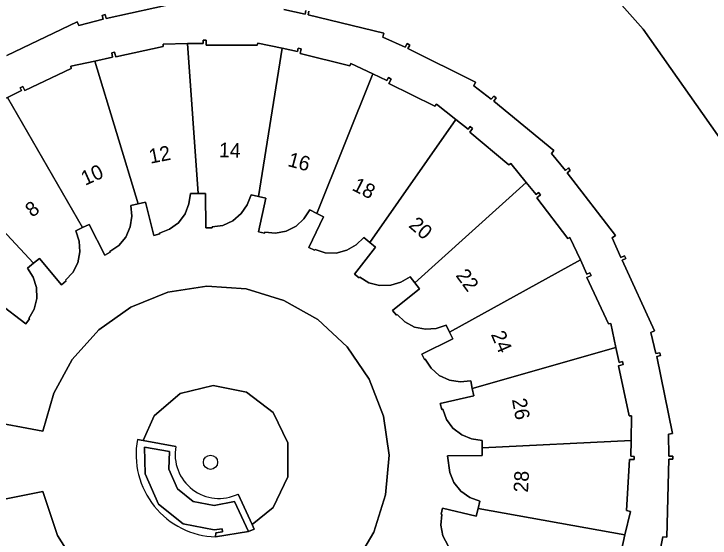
# Model space of a CAD drawing. Extents: x 156661 to 157576, y 383570 to 384425.
# Drawn here: x 157036.77 to 157084.57, y 384094.72 to 384130.69 of the extents above; entities that cross this region are included whole.
import ezdxf

# ---------------------------------------------------------------- set-up
doc = ezdxf.new("R2010")
doc.units = 0
for name, color, linetype in [('IMGEO_Boom', 7, 'Continuous'), ('IMGEO_Erf', 7, 'Continuous'), ('IMGEO_Groenvoorziening', 7, 'Continuous'), ('IMGEO_Muur', 7, 'Continuous'), ('IMGEO_Pand', 7, 'Continuous'), ('IMGEO_Pand_nummerreeks', 7, 'Continuous'), ('IMGEO_Voetpad_op_trap', 7, 'Continuous'), ('IMGEO_Voetpad_open', 7, 'Continuous')]:
    doc.layers.add(name, color=color, linetype=linetype)

msp = doc.modelspace()

# ---------------------------------------------------------------- linework, layer by layer
at = {"layer": 'IMGEO_Boom'}
msp.add_circle((157050.269, 384099.919), 0.489, dxfattribs=at)
at = {"layer": 'IMGEO_Erf'}
for points in [[(157048.127, 384131.481), (157043.095, 384130.384), (157043.028, 384130.645), (157042.825, 384130.593), (157042.892, 384130.331), (157041.237, 384129.908), (157041.118, 384130.156), (157036.279, 384127.836)], [(157056.821, 384130.939), (157056.767, 384130.675), (157055.294, 384130.999)], [(157081.016, 384093.338), (157081.32, 384094.794), (157081.594, 384094.785), (157081.74, 384100.134), (157082.004, 384100.136), (157082.002, 384100.346), (157081.732, 384100.344), (157081.712, 384101.851), (157081.981, 384101.906), (157080.903, 384107.175), (157081.167, 384107.238), (157081.114, 384107.441), (157080.852, 384107.378), (157080.506, 384108.824), (157080.756, 384108.939), (157078.531, 384113.785), (157078.779, 384113.906), (157078.69, 384114.097), (157078.447, 384113.978), (157077.845, 384115.335), (157078.07, 384115.495), (157074.758, 384119.784), (157074.967, 384119.956), (157074.843, 384120.125), (157074.634, 384119.954), (157073.675, 384121.103), (157073.85, 384121.316), (157069.713, 384124.714), (157069.878, 384124.928), (157069.712, 384125.057), (157069.547, 384124.843), (157068.349, 384125.76), (157068.471, 384126.007), (157063.82, 384128.317), (157063.951, 384128.554), (157063.767, 384128.655), (157063.636, 384128.418), (157062.103, 384129.096), (157062.167, 384129.363), (157056.97, 384130.62), (157057.026, 384130.889)], [(157036.336, 384124.956), (157037.285, 384125.441), (157037.192, 384125.629), (157037.375, 384125.722), (157037.52, 384125.433), (157040.705, 384126.94), (157040.67, 384127.096), (157042.322, 384127.458), (157043.551, 384127.728), (157043.486, 384128.025), (157043.689, 384128.077), (157043.759, 384127.755), (157047.016, 384128.46), (157047.013, 384128.62), (157048.696, 384128.653), (157049.758, 384128.674), (157049.758, 384128.894), (157049.963, 384128.895), (157049.968, 384128.557), (157053.482, 384128.539), (157053.513, 384128.69), (157055.178, 384128.34), (157056.236, 384128.118), (157056.281, 384128.332), (157056.487, 384128.289), (157056.42, 384127.967), (157059.829, 384127.14), (157059.896, 384127.285), (157061.423, 384126.576), (157062.384, 384126.129), (157062.482, 384126.321), (157062.666, 384126.22), (157062.52, 384125.924), (157065.677, 384124.365), (157065.776, 384124.491), (157067.112, 384123.451), (157067.96, 384122.79), (157068.1, 384122.96), (157068.267, 384122.832), (157068.065, 384122.57), (157070.755, 384120.324), (157070.879, 384120.426), (157071.944, 384119.12), (157072.619, 384118.293), (157072.79, 384118.432), (157072.924, 384118.27), (157072.669, 384118.06), (157074.801, 384115.28), (157074.946, 384115.347), (157075.659, 384113.804), (157076.105, 384112.84), (157076.305, 384112.932), (157076.397, 384112.743), (157076.103, 384112.593), (157077.589, 384109.42), (157077.743, 384109.453), (157078.106, 384107.804), (157078.332, 384106.778), (157078.547, 384106.826), (157078.596, 384106.621), (157078.276, 384106.541), (157079.005, 384103.114), (157079.167, 384103.112), (157079.148, 384101.408), (157079.135, 384100.331), (157079.355, 384100.328), (157079.357, 384100.118), (157079.027, 384100.116), (157078.828, 384096.611), (157079.099, 384096.548), (157078.725, 384094.94), (157078.48, 384093.889)], [(157066.574, 384094.189), (157066.219, 384094.872), (157066.086, 384095.611), (157066.157, 384096.342), (157066.099, 384096.354), (157066.187, 384096.769), (157068.518, 384096.231), (157068.635, 384096.738), (157068.752, 384097.245), (157068.073, 384097.504), (157067.465, 384097.934), (157066.973, 384098.522), (157066.689, 384099.217), (157066.549, 384100.373), (157068.91, 384100.382), (157068.916, 384100.901), (157068.923, 384101.42), (157068.195, 384101.526), (157067.519, 384101.798), (157066.902, 384102.259), (157066.462, 384102.866), (157066.208, 384103.555), (157066.15, 384103.541), (157066.047, 384103.963), (157068.347, 384104.487), (157068.24, 384104.995), (157068.133, 384105.503), (157067.4, 384105.448), (157066.68, 384105.565), (157065.978, 384105.88), (157065.415, 384106.376), (157065.017, 384106.993), (157064.963, 384106.966), (157064.775, 384107.347), (157066.895, 384108.385), (157066.674, 384108.854), (157066.453, 384109.324), (157065.752, 384109.102), (157065.025, 384109.051), (157064.27, 384109.197), (157063.608, 384109.551), (157063.079, 384110.06), (157063.033, 384110.022), (157062.765, 384110.346), (157064.609, 384111.819), (157064.292, 384112.23), (157063.974, 384112.641), (157063.338, 384112.272), (157062.64, 384112.065), (157061.87, 384112.043), (157061.148, 384112.245), (157060.521, 384112.627), (157060.484, 384112.58), (157060.159, 384112.833), (157061.607, 384114.69), (157061.203, 384115.015), (157060.799, 384115.341), (157060.266, 384114.835), (157059.634, 384114.471), (157058.891, 384114.271), (157058.141, 384114.3), (157057.443, 384114.527), (157057.418, 384114.472), (157057.019, 384114.654), (157058.024, 384116.777), (157057.558, 384117.006), (157057.093, 384117.236), (157056.683, 384116.626), (157056.147, 384116.132), (157055.465, 384115.775), (157054.727, 384115.639), (157053.996, 384115.707), (157053.984, 384115.648), (157053.563, 384115.736), (157054.061, 384118.037), (157053.556, 384118.156), (157053.05, 384118.274), (157052.79, 384117.586), (157052.379, 384116.984), (157051.796, 384116.481), (157051.108, 384116.182), (157050.381, 384116.082), (157050.382, 384116.022), (157049.952, 384116.013), (157049.93, 384118.372), (157049.411, 384118.376), (157048.892, 384118.379), (157048.789, 384117.652), (157048.522, 384116.974), (157048.065, 384116.354), (157047.46, 384115.91), (157046.772, 384115.653), (157046.787, 384115.594), (157046.381, 384115.493), (157045.812, 384117.778), (157045.3, 384117.659), (157044.788, 384117.54), (157044.858, 384116.808), (157044.755, 384116.087), (157044.455, 384115.378), (157043.97, 384114.805), (157043.361, 384114.395), (157043.389, 384114.342), (157043.012, 384114.146), (157041.945, 384116.251), (157041.479, 384116.024), (157041.012, 384115.797), (157041.243, 384115.099), (157041.304, 384114.373), (157041.169, 384113.615), (157040.824, 384112.949), (157040.322, 384112.413), (157040.361, 384112.367), (157040.038, 384112.093), (157038.527, 384113.904), (157038.119, 384113.575), (157037.712, 384113.246), (157038.094, 384112.618), (157038.316, 384111.924), (157038.354, 384111.155), (157038.167, 384110.428), (157037.799, 384109.793), (157037.847, 384109.757), (157037.593, 384109.417), (157035.706, 384110.832)], [(157034.816, 384102.793), (157038.761, 384102.061), (157039.52, 384104.666), (157040.782, 384106.976), (157042.603, 384109.015), (157044.809, 384110.57), (157047.332, 384111.598), (157050.022, 384112.012), (157052.72, 384111.821), (157055.311, 384111.02), (157057.647, 384109.712), (157059.648, 384107.839), (157061.16, 384105.616), (157062.145, 384103.084), (157062.541, 384100.402), (157062.288, 384097.687), (157061.477, 384095.127), (157060.112, 384092.793)], [(157041.241, 384092.533), (157039.761, 384094.89), (157038.769, 384097.919), (157034.843, 384097.129)]]:
    msp.add_lwpolyline(points, dxfattribs=at)
at = {"layer": 'IMGEO_Groenvoorziening'}
for points in [[(157027.895, 384067.5), (157043.532, 384046.733), (157047.525, 384049.683), (157080.513, 384071.09), (157084.345, 384074.369), (157089.926, 384085.599), (157092.747, 384099.97), (157093.567, 384107.816), (157092.136, 384111.936), (157085.938, 384121.166), (157079.977, 384129.642), (157075.189, 384135.046)], [(157075.189, 384135.046), (157079.977, 384129.642), (157085.938, 384121.166), (157092.136, 384111.936), (157093.567, 384107.816), (157092.747, 384099.97), (157089.926, 384085.599), (157084.345, 384074.369), (157087.624, 384070.536), (157154.965, 383981.147), (157118.076, 383955.713), (157048.492, 384046.401), (157047.525, 384049.683), (157043.532, 384046.733), (157050.307, 384037.736), (157052.866, 384034.354), (157120.283, 383944.64), (157124.325, 383946.137), (157128.805, 383949.146), (157133.769, 383943.405), (157129.807, 383939.447), (157125.958, 383936.438), (157125.242, 383934.934), (157125.69, 383934.221)], [(157036.279, 384127.836), (157041.118, 384130.156), (157041.237, 384129.908), (157042.892, 384130.331), (157042.825, 384130.593), (157043.028, 384130.645), (157043.095, 384130.384), (157048.127, 384131.481)], [(157055.294, 384130.999), (157056.767, 384130.675), (157056.821, 384130.939)], [(157057.026, 384130.889), (157056.97, 384130.62), (157062.167, 384129.363), (157062.103, 384129.096), (157063.636, 384128.418), (157063.767, 384128.655), (157063.951, 384128.554), (157063.82, 384128.317), (157068.471, 384126.007), (157068.349, 384125.76), (157069.547, 384124.843), (157069.712, 384125.057), (157069.878, 384124.928), (157069.713, 384124.714), (157073.85, 384121.316), (157073.675, 384121.103), (157074.634, 384119.954), (157074.843, 384120.125), (157074.967, 384119.956), (157074.758, 384119.784), (157078.07, 384115.495), (157077.845, 384115.335), (157078.447, 384113.978), (157078.69, 384114.097), (157078.779, 384113.906), (157078.531, 384113.785), (157080.756, 384108.939), (157080.506, 384108.824), (157080.852, 384107.378), (157081.114, 384107.441), (157081.167, 384107.238), (157080.903, 384107.175), (157081.981, 384101.906), (157081.712, 384101.851), (157081.732, 384100.344), (157082.002, 384100.346), (157082.004, 384100.136), (157081.74, 384100.134), (157081.594, 384094.785), (157081.32, 384094.794), (157081.016, 384093.338)], [(157052.173, 384097.739), (157053.118, 384095.645), (157054.576, 384096.825), (157055.587, 384098.918), (157055.578, 384101.249), (157054.564, 384103.331), (157052.733, 384104.728), (157050.45, 384105.185), (157048.187, 384104.63), (157046.408, 384103.115), (157045.656, 384101.41), (157047.892, 384101.009)]]:
    msp.add_lwpolyline(points, dxfattribs=at)
msp.add_arc((157050.859, 384100.457), 3.018, 169.4534, 295.7985, dxfattribs=at)
at = {"layer": 'IMGEO_Muur'}
for points in [[(157047.892, 384101.009), (157045.656, 384101.41), (157045.254, 384101.483)], [(157050.62, 384094.795), (157050.629, 384095.079), (157051.1, 384095.152), (157051.068, 384095.356), (157050.53, 384095.286), (157048.382, 384095.706), (157046.697, 384097.055), (157045.772, 384099.119), (157045.743, 384100.961), (157047.451, 384100.652), (157047.403, 384099.444), (157048.008, 384098.1), (157049.087, 384097.223), (157050.526, 384096.952), (157051.915, 384097.229), (157052.871, 384095.168), (157053.26, 384095.331), (157053.118, 384095.645), (157052.173, 384097.739)]]:
    msp.add_lwpolyline(points, dxfattribs=at)
for centre, radius, start, end in [((157050.826, 384100.457), 5.665, 169.5637, 267.9188), ((157050.859, 384100.457), 3.018, 169.4534, 295.7985)]:
    msp.add_arc(centre, radius, start, end, dxfattribs=at)
at = {"layer": 'IMGEO_Pand'}
for points in [[(157042.322, 384127.458), (157045.3, 384117.659), (157045.812, 384117.778), (157046.381, 384115.493), (157046.787, 384115.594), (157046.772, 384115.653), (157047.46, 384115.91), (157048.065, 384116.354), (157048.522, 384116.974), (157048.789, 384117.652), (157048.892, 384118.379), (157049.411, 384118.376), (157048.696, 384128.653), (157047.013, 384128.62), (157047.016, 384128.46), (157043.759, 384127.755), (157043.689, 384128.077), (157043.486, 384128.025), (157043.551, 384127.728)], [(157048.696, 384128.653), (157049.411, 384118.376), (157049.93, 384118.372), (157049.952, 384116.013), (157050.382, 384116.022), (157050.381, 384116.082), (157051.108, 384116.182), (157051.796, 384116.481), (157052.379, 384116.984), (157052.79, 384117.586), (157053.05, 384118.274), (157053.556, 384118.156), (157055.178, 384128.34), (157053.513, 384128.69), (157053.482, 384128.539), (157049.968, 384128.557), (157049.963, 384128.895), (157049.758, 384128.894), (157049.758, 384128.674)], [(157057.558, 384117.006), (157061.423, 384126.576), (157059.896, 384127.285), (157059.829, 384127.14), (157056.42, 384127.967), (157056.487, 384128.289), (157056.281, 384128.332), (157056.236, 384128.118), (157055.178, 384128.34), (157053.556, 384118.156), (157054.061, 384118.037), (157053.563, 384115.736), (157053.984, 384115.648), (157053.996, 384115.707), (157054.727, 384115.639), (157055.465, 384115.775), (157056.147, 384116.132), (157056.683, 384116.626), (157057.093, 384117.236)], [(157042.322, 384127.458), (157040.67, 384127.096), (157040.705, 384126.94), (157037.52, 384125.433), (157037.375, 384125.722), (157037.192, 384125.629), (157037.285, 384125.441), (157036.336, 384124.956), (157041.479, 384116.024), (157041.945, 384116.251), (157043.012, 384114.146), (157043.389, 384114.342), (157043.361, 384114.395), (157043.97, 384114.805), (157044.455, 384115.378), (157044.755, 384116.087), (157044.858, 384116.808), (157044.788, 384117.54), (157045.3, 384117.659)], [(157057.558, 384117.006), (157058.024, 384116.777), (157057.019, 384114.654), (157057.418, 384114.472), (157057.443, 384114.527), (157058.141, 384114.3), (157058.891, 384114.271), (157059.634, 384114.471), (157060.266, 384114.835), (157060.799, 384115.341), (157061.203, 384115.015), (157067.112, 384123.451), (157065.776, 384124.491), (157065.677, 384124.365), (157062.52, 384125.924), (157062.666, 384126.22), (157062.482, 384126.321), (157062.384, 384126.129), (157061.423, 384126.576)], [(157031.102, 384121.115), (157038.119, 384113.575), (157038.527, 384113.904), (157040.038, 384112.093), (157040.361, 384112.367), (157040.322, 384112.413), (157040.824, 384112.949), (157041.169, 384113.615), (157041.304, 384114.373), (157041.243, 384115.099), (157041.012, 384115.797), (157041.479, 384116.024), (157036.336, 384124.956), (157034.832, 384124.186), (157034.906, 384124.041), (157032.139, 384121.853), (157031.944, 384122.1), (157031.788, 384121.968), (157031.914, 384121.8)], [(157064.292, 384112.23), (157071.944, 384119.12), (157070.879, 384120.426), (157070.755, 384120.324), (157068.065, 384122.57), (157068.267, 384122.832), (157068.1, 384122.96), (157067.96, 384122.79), (157067.112, 384123.451), (157061.203, 384115.015), (157061.607, 384114.69), (157060.159, 384112.833), (157060.484, 384112.58), (157060.521, 384112.627), (157061.148, 384112.245), (157061.87, 384112.043), (157062.64, 384112.065), (157063.338, 384112.272), (157063.974, 384112.641)], [(157031.102, 384121.115), (157029.814, 384120.027), (157029.919, 384119.902), (157027.713, 384117.136), (157027.45, 384117.345), (157027.336, 384117.178), (157027.498, 384117.048), (157026.859, 384116.199), (157035.386, 384110.419), (157035.706, 384110.832), (157037.593, 384109.417), (157037.847, 384109.757), (157037.799, 384109.793), (157038.167, 384110.428), (157038.354, 384111.155), (157038.316, 384111.924), (157038.094, 384112.618), (157037.712, 384113.246), (157038.119, 384113.575)], [(157064.292, 384112.23), (157064.609, 384111.819), (157062.765, 384110.346), (157063.033, 384110.022), (157063.079, 384110.06), (157063.608, 384109.551), (157064.27, 384109.197), (157065.025, 384109.051), (157065.752, 384109.102), (157066.453, 384109.324), (157066.674, 384108.854), (157075.659, 384113.804), (157074.946, 384115.347), (157074.801, 384115.28), (157072.669, 384118.06), (157072.924, 384118.27), (157072.79, 384118.432), (157072.619, 384118.293), (157071.944, 384119.12)], [(157068.24, 384104.995), (157078.106, 384107.804), (157077.743, 384109.453), (157077.589, 384109.42), (157076.103, 384112.593), (157076.397, 384112.743), (157076.305, 384112.932), (157076.105, 384112.84), (157075.659, 384113.804), (157066.674, 384108.854), (157066.895, 384108.385), (157064.775, 384107.347), (157064.963, 384106.966), (157065.017, 384106.993), (157065.415, 384106.376), (157065.978, 384105.88), (157066.68, 384105.565), (157067.4, 384105.448), (157068.133, 384105.503)], [(157068.24, 384104.995), (157068.347, 384104.487), (157066.047, 384103.963), (157066.15, 384103.541), (157066.208, 384103.555), (157066.462, 384102.866), (157066.902, 384102.259), (157067.519, 384101.798), (157068.195, 384101.526), (157068.923, 384101.42), (157068.916, 384100.901), (157079.148, 384101.408), (157079.167, 384103.112), (157079.005, 384103.114), (157078.276, 384106.541), (157078.596, 384106.621), (157078.547, 384106.826), (157078.332, 384106.778), (157078.106, 384107.804)], [(157078.725, 384094.94), (157079.099, 384096.548), (157078.828, 384096.611), (157079.027, 384100.116), (157079.357, 384100.118), (157079.355, 384100.328), (157079.135, 384100.331), (157079.148, 384101.408), (157068.916, 384100.901), (157068.91, 384100.382), (157066.549, 384100.373), (157066.689, 384099.217), (157066.973, 384098.522), (157067.465, 384097.934), (157068.073, 384097.504), (157068.752, 384097.245), (157068.635, 384096.738)], [(157067.442, 384092.774), (157076.888, 384088.72), (157077.609, 384090.219), (157077.474, 384090.284), (157078.317, 384093.699), (157078.651, 384093.626), (157078.695, 384093.839), (157078.48, 384093.889), (157078.725, 384094.94), (157068.635, 384096.738), (157068.518, 384096.231), (157066.187, 384096.769), (157066.099, 384096.354), (157066.157, 384096.342), (157066.086, 384095.611), (157066.219, 384094.872), (157066.574, 384094.189), (157067.065, 384093.651), (157067.674, 384093.239)]]:
    msp.add_lwpolyline(points, close=True, dxfattribs=at)
at = {"layer": 'IMGEO_Voetpad_op_trap'}
msp.add_lwpolyline([(157047.403, 384099.444), (157047.451, 384100.652), (157045.743, 384100.961), (157045.772, 384099.119), (157046.697, 384097.055), (157048.382, 384095.706), (157050.53, 384095.286), (157051.068, 384095.356), (157051.1, 384095.152), (157050.629, 384095.079), (157050.62, 384094.795), (157052.871, 384095.168), (157051.915, 384097.229), (157050.526, 384096.952), (157049.087, 384097.223), (157048.008, 384098.1)], close=True, dxfattribs=at)
at = {"layer": 'IMGEO_Voetpad_open'}
for points in [[(157060.112, 384092.793), (157061.477, 384095.127), (157062.288, 384097.687), (157062.541, 384100.402), (157062.145, 384103.084), (157061.16, 384105.616), (157059.648, 384107.839), (157057.647, 384109.712), (157055.311, 384111.02), (157052.72, 384111.821), (157050.022, 384112.012), (157047.332, 384111.598), (157044.809, 384110.57), (157042.603, 384109.015), (157040.782, 384106.976), (157039.52, 384104.666), (157038.761, 384102.061), (157034.816, 384102.793)], [(157045.254, 384101.483), (157045.656, 384101.41), (157046.408, 384103.115), (157048.187, 384104.63), (157050.45, 384105.185), (157052.733, 384104.728), (157054.564, 384103.331), (157055.578, 384101.249), (157055.587, 384098.918), (157054.576, 384096.825), (157053.118, 384095.645), (157053.26, 384095.331), (157052.871, 384095.168), (157050.62, 384094.795)], [(157034.843, 384097.129), (157038.769, 384097.919), (157039.761, 384094.89), (157041.241, 384092.533)]]:
    msp.add_lwpolyline(points, dxfattribs=at)
msp.add_arc((157050.826, 384100.457), 5.665, 169.5637, 267.9188, dxfattribs=at)

# ---------------------------------------------------------------- texts
at = {"layer": 'IMGEO_Pand_nummerreeks'}
for s, rotation, p in [('14', 358.1865, (157050.838, 384120.865)), ('12', 11.0576, (157046.143, 384120.41)), ('16', 345.1896, (157055.513, 384120.26)), ('10', 24.3912, (157041.662, 384118.89)), ('18', 332.6488, (157059.921, 384118.632)), ('8', 37.3011, (157038.029, 384116.692)), ('20', 319.1246, (157063.819, 384116.107)), ('22', 306.4695, (157067.064, 384112.737)), ('24', 293.2529, (157069.504, 384108.695)), ('26', 280.6264, (157070.96, 384104.228)), ('28', 87.1239, (157072.066, 384097.829))]:
    msp.add_text(s, height=1, rotation=rotation, dxfattribs=at).set_placement(p)

doc.saveas('drawing.dxf')
